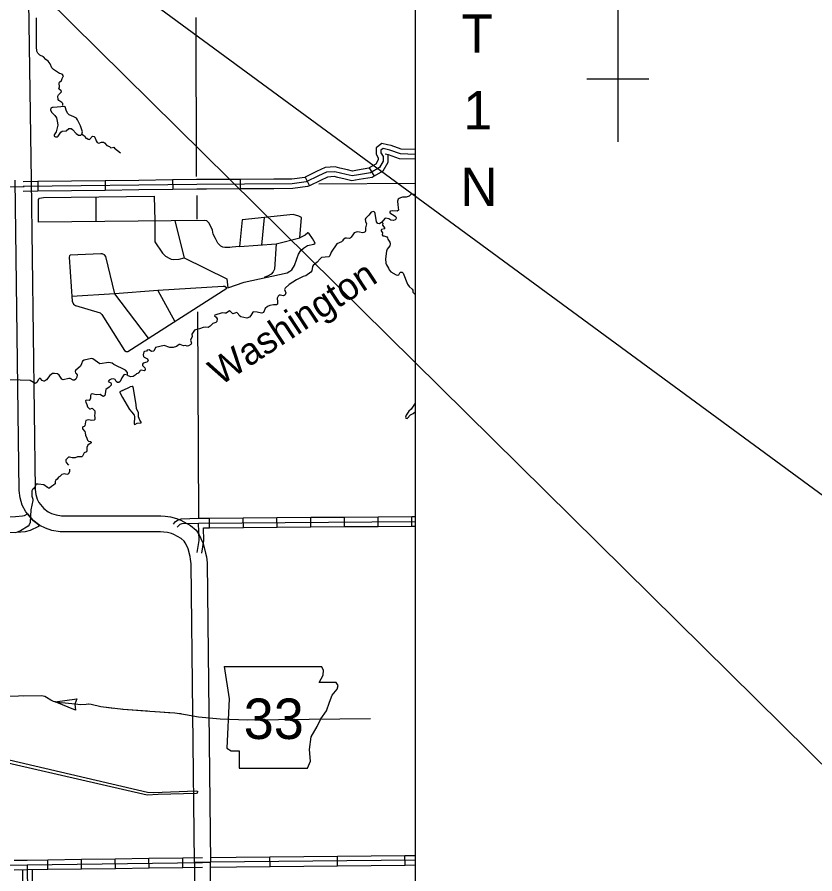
# Model space of a CAD drawing. Extents: x 982240 to 1103002, y 974866 to 1054902.
# Drawn here: x 1057609 to 1070096, y 991826 to 1005242 of the extents above; entities that cross this region are included whole.
import ezdxf

# ---------------------------------------------------------------- set-up
doc = ezdxf.new("R2010")
doc.units = 0
for name, color, linetype in [('10', 7, 'Continuous'), ('21', 7, 'Continuous'), ('31', 7, 'Continuous'), ('32', 7, 'Continuous'), ('35', 7, 'Continuous'), ('43', 7, 'Continuous'), ('45', 7, 'Continuous'), ('5', 7, 'Continuous'), ('R_Draft', 7, 'Continuous')]:
    doc.layers.add(name, color=color, linetype=linetype)

msp = doc.modelspace()

# ---------------------------------------------------------------- linework, layer by layer
at = {"layer": '10'}
for p, q in [((1059250, 997434), (1059251, 997434)), ((1060637, 992006), (1060387, 992005)), ((1060637, 992006), (1060387, 992005))]:
    msp.add_line(p, q, dxfattribs=at)
for points in [[(1057779, 1006192), (1057828, 1002691)], [(1059251, 997184), (1058283, 997180), (1058154, 997205), (1058053, 997239), (1057965, 997282), (1057854, 997364), (1057744, 997497), (1057688, 997597), (1057654, 997715), (1057641, 997828), (1057578, 1002688)], [(1057828, 1002691), (1057891, 997844), (1057900, 997764), (1057921, 997693), (1057951, 997639), (1058027, 997547), (1058095, 997497), (1058149, 997471), (1058218, 997447), (1058306, 997430), (1059250, 997434)], [(1050151, 997289), (1052347, 997337), (1057585, 997420), (1057692, 997430), (1057722, 997438), (1057772, 997463)], [(1057772, 997463), (1057854, 997364), (1057965, 997282)], [(1059251, 997434), (1059859, 997430), (1059924, 997427), (1060008, 997419), (1060106, 997393), (1060171, 997366), (1060323, 997280), (1060409, 997206), (1060460, 997134), (1060486, 997075), (1060520, 997000), (1060560, 996850), (1060572, 996791), (1060582, 996697), (1060637, 992007)], [(1057964, 997283), (1057942, 997268), (1057811, 997203), (1057737, 997183), (1057598, 997170), (1052351, 997087), (1050156, 997039)], [(1060387, 992004), (1060332, 996682), (1060325, 996753), (1060316, 996794), (1060284, 996916), (1060259, 996971), (1060241, 997009), (1060222, 997038), (1060179, 997075), (1060061, 997141), (1060025, 997156), (1059965, 997172), (1059906, 997177), (1059852, 997180), (1059249, 997184)], [(1060387, 992005), (1060415, 987556)], [(1060665, 987556), (1060637, 992006)]]:
    msp.add_lwpolyline(points, dxfattribs=at)
at = {"layer": '21'}
for p, q in [((1060850, 995073), (1060926, 994566)), ((1062406, 995014), (1062371, 995073)), ((1062339, 994820), (1062398, 994938)), ((1062398, 994938), (1062406, 995014)), ((1062601, 994820), (1062339, 994820)), ((1062635, 994777), (1062601, 994820)), ((1062618, 994718), (1062635, 994777)), ((1062542, 994625), (1062618, 994718)), ((1060926, 994566), (1060892, 993796)), ((1062449, 994380), (1062499, 994515)), ((1062499, 994515), (1062542, 994625)), ((1062364, 994253), (1062449, 994380)), ((1062305, 994135), (1062364, 994253)), ((1062212, 993974), (1062305, 994135)), ((1062186, 993771), (1062212, 993974)), ((1060892, 993796), (1060960, 993754)), ((1060960, 993754), (1061087, 993754)), ((1061087, 993754), (1061087, 993483)), ((1062203, 993593), (1062186, 993771)), ((1062152, 993483), (1062203, 993593)), ((1061087, 993483), (1062152, 993483))]:
    msp.add_line(p, q, dxfattribs=at)
msp.add_lwpolyline([(1060850, 995073), (1062371, 995073)], dxfattribs=at)
at = {"layer": '31'}
for p, q in [((1057694, 991892), (1057700, 991437)), ((1057844, 991894), (1057850, 991439))]:
    msp.add_line(p, q, dxfattribs=at)
msp.add_lwpolyline([(1057767, 991966), (1057800, 989237), (1057819, 988343)], dxfattribs=at)
at = {"layer": '32'}
for p, q in [((1060622, 997247), (1060620, 997397)), ((1061150, 997251), (1061148, 997401)), ((1061678, 997255), (1061676, 997405)), ((1062206, 997259), (1062204, 997409)), ((1062734, 997263), (1062732, 997413)), ((1063262, 997268), (1063260, 997418)), ((1063789, 997272), (1063788, 997422)), ((1060524, 997246), (1060622, 997247)), ((1058092, 991897), (1058089, 992047)), ((1058619, 991905), (1058617, 992055)), ((1059147, 991912), (1059145, 992062)), ((1059675, 991920), (1059673, 992070)), ((1060203, 991927), (1060201, 992077))]:
    msp.add_line(p, q, dxfattribs=at)
for points in [[(1060056, 997300), (1060089, 997343), (1060128, 997371), (1060178, 997387), (1060446, 997395), (1060620, 997397)], [(1060116, 997253), (1060143, 997288), (1060162, 997302), (1060191, 997311), (1060448, 997319), (1063840, 997346)], [(1060429, 996857), (1060456, 997048), (1060448, 997319)], [(1060620, 997397), (1061148, 997401)], [(1061148, 997401), (1061676, 997405)], [(1061676, 997405), (1062204, 997409)], [(1062204, 997409), (1062732, 997413)], [(1062732, 997413), (1063260, 997418)], [(1063260, 997418), (1063788, 997422)], [(1063788, 997422), (1063840, 997422)], [(1060502, 996847), (1060530, 997044), (1060524, 997246)], [(1060622, 997247), (1061150, 997251)], [(1061150, 997251), (1061678, 997255)], [(1061678, 997255), (1062206, 997259)], [(1062206, 997259), (1062734, 997263)], [(1062734, 997263), (1063262, 997268)], [(1063262, 997268), (1063789, 997272)], [(1063789, 997272), (1063840, 997272)], [(1049643, 991895), (1055029, 991939), (1057767, 991966)], [(1057562, 992041), (1057766, 992043), (1058089, 992047)], [(1057767, 991966), (1060512, 992005)], [(1058089, 992047), (1058617, 992055)], [(1058617, 992055), (1059145, 992062)], [(1059145, 992062), (1059673, 992070)], [(1059673, 992070), (1060201, 992077)], [(1060201, 992077), (1060511, 992082)], [(1057563, 991891), (1057768, 991893), (1058092, 991897)], [(1058092, 991897), (1058619, 991905)], [(1058619, 991905), (1059147, 991912)], [(1059147, 991912), (1059675, 991920)], [(1059675, 991920), (1060203, 991927)], [(1060203, 991927), (1060513, 991932)]]:
    msp.add_lwpolyline(points, dxfattribs=at)
at = {"layer": '35'}
for points in [[(1058323, 1003856), (1058326, 1003876), (1058323, 1003890), (1058311, 1003904), (1058262, 1003937), (1058252, 1003954), (1058245, 1004005), (1058257, 1004024), (1058303, 1004070), (1058299, 1004086), (1058265, 1004112), (1058262, 1004120), (1058272, 1004151), (1058268, 1004209), (1058272, 1004222), (1058302, 1004249), (1058312, 1004280), (1058332, 1004310), (1058333, 1004325), (1058315, 1004347), (1058274, 1004358), (1058239, 1004381), (1058180, 1004422), (1058151, 1004448), (1058124, 1004511), (1058097, 1004554), (1058057, 1004579), (1058021, 1004620), (1057967, 1004646), (1057933, 1004676), (1057916, 1004708), (1057910, 1004777), (1057911, 1005233)], [(1058173, 1003825), (1058156, 1003824), (1058136, 1003815), (1058131, 1003791), (1058149, 1003756), (1058201, 1003699), (1058224, 1003666), (1058241, 1003589), (1058246, 1003549), (1058220, 1003445), (1058190, 1003401), (1058188, 1003376), (1058209, 1003366), (1058239, 1003369), (1058253, 1003378), (1058293, 1003441), (1058313, 1003457), (1058374, 1003459), (1058416, 1003499), (1058454, 1003496), (1058477, 1003481), (1058533, 1003418), (1058571, 1003392), (1058605, 1003391), (1058621, 1003407), (1058631, 1003448)], [(1058631, 1003448), (1058603, 1003537), (1058554, 1003635), (1058536, 1003659), (1058499, 1003680), (1058425, 1003712), (1058403, 1003732), (1058381, 1003771), (1058363, 1003835), (1058354, 1003840), (1058173, 1003825)], [(1058621, 1003407), (1058661, 1003381), (1058683, 1003346), (1058702, 1003347), (1058722, 1003331), (1058741, 1003326), (1058790, 1003376), (1058817, 1003372), (1058825, 1003364), (1058845, 1003306), (1058864, 1003280), (1058890, 1003268), (1058929, 1003282), (1058959, 1003283), (1058976, 1003273), (1059014, 1003234), (1059057, 1003214), (1059078, 1003197), (1059122, 1003203), (1059134, 1003189), (1059225, 1003115)], [(1058022, 1002416), (1059755, 1002439)], [(1058844, 1002041), (1058844, 1002427)], [(1059755, 1002439), (1059765, 1002051), (1059762, 1001725), (1059886, 1001546), (1059934, 1001496), (1059997, 1001464)], [(1063840, 1002451), (1063818, 1002465), (1063779, 1002467), (1063760, 1002456), (1063747, 1002439), (1063700, 1002420), (1063639, 1002420), (1063611, 1002414), (1063591, 1002404), (1063574, 1002389), (1063565, 1002359), (1063570, 1002301), (1063581, 1002220), (1063556, 1002202), (1063485, 1002207), (1063453, 1002203), (1063443, 1002196), (1063445, 1002176), (1063526, 1002126), (1063538, 1002114), (1063542, 1002099), (1063537, 1002080), (1063528, 1002069), (1063499, 1002055), (1063461, 1002062), (1063427, 1002085), (1063379, 1002095), (1063363, 1002091), (1063318, 1002030)], [(1057941, 1002029), (1057943, 1002388), (1057958, 1002409), (1058022, 1002416)], [(1059997, 1001464), (1060021, 1001453), (1060054, 1001446), (1060145, 1001451), (1060224, 1001472), (1060889, 1001145), (1060906, 1001001), (1061165, 1001094), (1061837, 1001240), (1061877, 1001262), (1061911, 1001287), (1061952, 1001352), (1061985, 1001459), (1062015, 1001528), (1062050, 1001585), (1062094, 1001626), (1062155, 1001665), (1062251, 1001688), (1062274, 1001702), (1062232, 1001774), (1062177, 1001857), (1062161, 1001866), (1062117, 1001826), (1062032, 1001785), (1062061, 1002105), (1062020, 1002126), (1061928, 1002151), (1061134, 1002070), (1061091, 1001649), (1060973, 1001640), (1060937, 1001632), (1060860, 1001633), (1060829, 1001639), (1060795, 1001653), (1060753, 1001703), (1060712, 1001775), (1060680, 1001843), (1060666, 1001906), (1060616, 1002017), (1060578, 1002053), (1060544, 1002058), (1057941, 1002029)], [(1063318, 1002030), (1063282, 1002004), (1063255, 1002008), (1063236, 1002036), (1063215, 1002166), (1063207, 1002182), (1063191, 1002196), (1063172, 1002195), (1063150, 1002186), (1063116, 1002143), (1063065, 1002096), (1063055, 1002080), (1063062, 1002043), (1063078, 1002006), (1063062, 1001944), (1063063, 1001891), (1063057, 1001879), (1063038, 1001868), (1063017, 1001866), (1062966, 1001877), (1062932, 1001878), (1062886, 1001865), (1062862, 1001833), (1062840, 1001796), (1062823, 1001779), (1062809, 1001776), (1062766, 1001782), (1062744, 1001779), (1062711, 1001755), (1062704, 1001739), (1062685, 1001723), (1062615, 1001694), (1062525, 1001561), (1062505, 1001502), (1062486, 1001487), (1062375, 1001477), (1062352, 1001458), (1062308, 1001407), (1062242, 1001351), (1062231, 1001336), (1062220, 1001271), (1062206, 1001246), (1062130, 1001189), (1062084, 1001178), (1061984, 1001130), (1061868, 1001053), (1061803, 1000996), (1061794, 1000975), (1061816, 1000926), (1061804, 1000895), (1061790, 1000885), (1061774, 1000880), (1061732, 1000889), (1061711, 1000888), (1061693, 1000874), (1061679, 1000843), (1061685, 1000785)], [(1060076, 1002053), (1060224, 1001472)], [(1061478, 1002105), (1061433, 1001673)], [(1063318, 1002030), (1063333, 1002017), (1063327, 1001984), (1063349, 1001960), (1063364, 1001933), (1063360, 1001926), (1063312, 1001914), (1063306, 1001905), (1063306, 1001895), (1063327, 1001864), (1063323, 1001835), (1063335, 1001818), (1063350, 1001816), (1063395, 1001803), (1063405, 1001787), (1063412, 1001765), (1063442, 1001717), (1063447, 1001691), (1063444, 1001662), (1063402, 1001610), (1063390, 1001579), (1063377, 1001456), (1063382, 1001390), (1063389, 1001361), (1063423, 1001311), (1063433, 1001282), (1063456, 1001253), (1063544, 1001205), (1063566, 1001199), (1063585, 1001205), (1063601, 1001238), (1063612, 1001248), (1063635, 1001249), (1063651, 1001231), (1063721, 1001058), (1063746, 1001021), (1063793, 1000984), (1063801, 1000967), (1063805, 1000933), (1063840, 1000900)], [(1061091, 1001649), (1061666, 1001691), (1062032, 1001785)], [(1061666, 1001691), (1061637, 1001296), (1061619, 1001253), (1061587, 1001218), (1061541, 1001190), (1061475, 1001163)], [(1060893, 1000997), (1060862, 1001021), (1060836, 1001025), (1059810, 1000959), (1059139, 1000909), (1058995, 1001493), (1058977, 1001521), (1058941, 1001534), (1058917, 1001536), (1058441, 1001516), (1058429, 1001504), (1058426, 1001482), (1058471, 1000792), (1058489, 1000749), (1058524, 1000724), (1058911, 1000611), (1058935, 1000585), (1059291, 1000022), (1059315, 1000008), (1059340, 1000007), (1060893, 1000997)], [(1059810, 1000959), (1060076, 1000478)], [(1059667, 1000215), (1059139, 1000909), (1058467, 1000868)], [(1061685, 1000785), (1061683, 1000745), (1061668, 1000736), (1061620, 1000739), (1061563, 1000727), (1061526, 1000712), (1061491, 1000679), (1061465, 1000614), (1061439, 1000605), (1061389, 1000614), (1061365, 1000623), (1061310, 1000628), (1061297, 1000622), (1061269, 1000567), (1061247, 1000543), (1061205, 1000526), (1061110, 1000549), (1061086, 1000568), (1061075, 1000588), (1061055, 1000609), (1061042, 1000616), (1061015, 1000606), (1060985, 1000595), (1060945, 1000638), (1060934, 1000640), (1060882, 1000604), (1060858, 1000604), (1060820, 1000612), (1060703, 1000574), (1060699, 1000563), (1060727, 1000546), (1060742, 1000518), (1060737, 1000475), (1060719, 1000458), (1060671, 1000445), (1060630, 1000402), (1060598, 1000380), (1060550, 1000387), (1060520, 1000382), (1060463, 1000359), (1060402, 1000347), (1060384, 1000339), (1060344, 1000279), (1060349, 1000240), (1060324, 1000183), (1060337, 1000134), (1060329, 1000113), (1060294, 1000093), (1060273, 1000091), (1060245, 1000098), (1060214, 1000093), (1060159, 1000115), (1060143, 1000113), (1060105, 1000086), (1060049, 1000068)], [(1060049, 1000068), (1060000, 1000069), (1059909, 1000098), (1059777, 1000070), (1059747, 1000011), (1059714, 1000005), (1059678, 1000032), (1059645, 1000026), (1059633, 1000012), (1059605, 1000006), (1059594, 999998), (1059580, 999954), (1059585, 999930), (1059595, 999916), (1059648, 999890), (1059659, 999861), (1059655, 999852), (1059637, 999839), (1059583, 999822), (1059570, 999805), (1059573, 999784), (1059609, 999748), (1059615, 999728), (1059613, 999713), (1059598, 999704), (1059549, 999713), (1059536, 999706), (1059513, 999674), (1059497, 999661), (1059480, 999657), (1059471, 999645), (1059426, 999615), (1059389, 999611), (1059346, 999625), (1059336, 999634)], [(1059336, 999634), (1059336, 999675), (1059306, 999714), (1059125, 999800), (1059097, 999821), (1059042, 999833), (1058901, 999813), (1058794, 999890), (1058772, 999895), (1058658, 999871), (1058634, 999854), (1058615, 999814), (1058599, 999774), (1058522, 999706), (1058516, 999691), (1058524, 999670), (1058535, 999663), (1058547, 999642), (1058546, 999603), (1058530, 999573), (1058505, 999558), (1058487, 999556), (1058437, 999581), (1058416, 999585), (1058331, 999561), (1058310, 999573), (1058268, 999635), (1058243, 999656), (1058194, 999663), (1058165, 999661), (1058123, 999632), (1058070, 999564), (1058037, 999543), (1058026, 999541), (1057999, 999554), (1057976, 999582), (1057965, 999587), (1057946, 999568), (1057915, 999520), (1057891, 999507), (1057815, 999554), (1056697, 999590)], [(1059336, 999634), (1059290, 999647), (1059277, 999640), (1059250, 999592), (1059222, 999535), (1059200, 999521), (1059180, 999522), (1059161, 999538), (1059143, 999569), (1059117, 999577), (1059081, 999572), (1059050, 999558), (1059032, 999537), (1059077, 999514), (1059082, 999503), (1059082, 999481), (1059051, 999445), (1058998, 999409), (1058990, 999386), (1058988, 999337), (1058981, 999315), (1058960, 999303), (1058945, 999306), (1058907, 999334), (1058844, 999327), (1058802, 999340), (1058782, 999341), (1058769, 999337), (1058755, 999315), (1058757, 999277), (1058752, 999258), (1058739, 999241), (1058690, 999245), (1058681, 999234), (1058685, 999212), (1058700, 999176), (1058711, 999139), (1058742, 999109), (1058759, 999108), (1058782, 999119), (1058824, 999077), (1058824, 999041), (1058820, 999000), (1058826, 998970), (1058824, 998942), (1058815, 998932), (1058776, 998926), (1058726, 998936), (1058684, 998925), (1058677, 998907), (1058671, 998844), (1058657, 998831), (1058639, 998824), (1058630, 998809), (1058632, 998793)], [(1059260, 999397), (1059219, 999376), (1059217, 999365), (1059257, 999287), (1059370, 999097), (1059404, 999056), (1059439, 999011), (1059445, 998986), (1059441, 998870), (1059454, 998861), (1059488, 998883), (1059551, 998889), (1059552, 998898), (1059529, 998932), (1059511, 998984), (1059508, 999044), (1059475, 999113), (1059472, 999170), (1059433, 999424), (1059418, 999457), (1059412, 999458), (1059376, 999452)], [(1059260, 999397), (1059376, 999452)], [(1063840, 999195), (1063776, 999105), (1063739, 999071), (1063700, 999009), (1063689, 998975), (1063692, 998960), (1063712, 998958), (1063766, 999012), (1063808, 999035), (1063840, 999062)], [(1058632, 998793), (1058667, 998754), (1058676, 998731), (1058680, 998694), (1058702, 998649), (1058710, 998615), (1058726, 998601), (1058757, 998594), (1058768, 998587), (1058770, 998577), (1058716, 998539), (1058701, 998505), (1058699, 998448), (1058693, 998437), (1058659, 998417), (1058634, 998365), (1058622, 998355), (1058553, 998357), (1058520, 998343), (1058473, 998342), (1058429, 998352), (1058412, 998349), (1058390, 998332), (1058370, 998307), (1058369, 998291), (1058375, 998267), (1058415, 998225)], [(1058429, 998165), (1058427, 998125), (1058414, 998092), (1058404, 998084), (1058387, 998080), (1058348, 998088), (1058328, 998086), (1058309, 998078), (1058279, 998047), (1058258, 998036), (1058235, 998005), (1058215, 997992), (1058203, 997972), (1058205, 997936), (1058179, 997915), (1058147, 997894), (1058114, 997867), (1058101, 997864), (1058082, 997874), (1058025, 997918), (1057937, 997929), (1057905, 997926), (1057896, 997913), (1057889, 997892), (1057863, 997857), (1057848, 997847), (1057837, 997825), (1057840, 997741), (1057854, 997695), (1057856, 997672), (1057824, 997529), (1057813, 997326), (1057800, 997293), (1057784, 997272), (1057664, 997198), (1057585, 997168)], [(1057485, 993614), (1059648, 993103), (1059743, 993102), (1060412, 993128), (1060430, 993123), (1060434, 993111), (1060427, 993092), (1060409, 993082), (1059815, 993069), (1059645, 993058), (1056506, 993781)]]:
    msp.add_lwpolyline(points, dxfattribs=at)
at = {"layer": '43'}
for p, q in [((1058207, 994518), (1058546, 994567)), ((1058525, 994390), (1058207, 994518)), ((1058546, 994567), (1058513, 994482)), ((1058512, 994481), (1058525, 994390))]:
    msp.add_line(p, q, dxfattribs=at)
for points in [[(1063138, 994254), (1061218, 994232), (1060789, 994251), (1060449, 994279), (1060247, 994317), (1060151, 994334), (1060075, 994343), (1059686, 994369), (1059269, 994401), (1058917, 994442), (1058768, 994476), (1058724, 994483), (1058689, 994477), (1058603, 994473), (1058515, 994481), (1058363, 994501), (1058283, 994505), (1058237, 994512), (1058177, 994525), (1058137, 994548), (1058071, 994590), (1058042, 994605), (1058016, 994610), (1057988, 994613), (1055091, 994574)], [(1058092, 994577), (1058071, 994590), (1058042, 994605), (1058016, 994610), (1057988, 994613), (1057704, 994609)], [(1058601, 994473), (1058515, 994481), (1058363, 994501), (1058283, 994505), (1058237, 994512), (1058208, 994518)], [(1059123, 994418), (1058917, 994442), (1058768, 994476), (1058732, 994482)], [(1059649, 994372), (1059269, 994401), (1059254, 994403)], [(1059978, 994349), (1059780, 994362)], [(1060175, 994330), (1060151, 994334), (1060075, 994343), (1059978, 994349)]]:
    msp.add_lwpolyline(points, dxfattribs=at)
at = {"layer": '45'}
for p, q in [((1063121, 1002880), (1063197, 1002751)), ((1060042, 1002693), (1060044, 1002543)), ((1061099, 1002701), (1061100, 1002551)), ((1062118, 1002737), (1062184, 1002602)), ((1057931, 1002666), (1057932, 1002516)), ((1058986, 1002679), (1058988, 1002529)), ((1061569, 991941), (1061567, 992091)), ((1062625, 991953), (1062623, 992103)), ((1063681, 991964), (1063679, 992114)), ((1063840, 992040), (1060637, 992007)), ((1063840, 992040), (1060637, 992007))]:
    msp.add_line(p, q, dxfattribs=at)
for points in [[(1063404, 1003243), (1063320, 1003263), (1063229, 1003195), (1063229, 1003096), (1063262, 1003039), (1063262, 1003005), (1063224, 1002941), (1063121, 1002880)], [(1063840, 1003168), (1063622, 1003174), (1063465, 1003229), (1063404, 1003243)], [(1063840, 1003093), (1063608, 1003100), (1063444, 1003157), (1063337, 1003182), (1063304, 1003157), (1063304, 1003116), (1063337, 1003059), (1063337, 1002985), (1063279, 1002886), (1063140, 1002804), (1062951, 1002771), (1062852, 1002754), (1062761, 1002779), (1062581, 1002820), (1062449, 1002812), (1062326, 1002754), (1062131, 1002660), (1061916, 1002631), (1060420, 1002623), (1057704, 1002588)], [(1063406, 1003089), (1063412, 1003078), (1063412, 1002964), (1063334, 1002831), (1063197, 1002751)], [(1063840, 1003018), (1063594, 1003025), (1063423, 1003085), (1063371, 1003097)], [(1062662, 1002878), (1062587, 1002896), (1062430, 1002886), (1062294, 1002822), (1062118, 1002737)], [(1063121, 1002880), (1063113, 1002875), (1062938, 1002845), (1062856, 1002831), (1062780, 1002852), (1062662, 1002878)], [(1059514, 1002686), (1058986, 1002679)], [(1060042, 1002693), (1059514, 1002686)], [(1060571, 1002699), (1060419, 1002698), (1060042, 1002693)], [(1061099, 1002701), (1060571, 1002699)], [(1061627, 1002704), (1061099, 1002701)], [(1062118, 1002737), (1062110, 1002733), (1061911, 1002706), (1061627, 1002704)], [(1062628, 1002732), (1062574, 1002744), (1062468, 1002738), (1062358, 1002686), (1062184, 1002602)], [(1063197, 1002751), (1063166, 1002732), (1062963, 1002697), (1062848, 1002678), (1062743, 1002706), (1062628, 1002732)], [(1057931, 1002666), (1057703, 1002663)], [(1058459, 1002673), (1057931, 1002666)], [(1058986, 1002679), (1058459, 1002673)], [(1061100, 1002551), (1060572, 1002549)], [(1061628, 1002554), (1061100, 1002551)], [(1062184, 1002602), (1062153, 1002588), (1061922, 1002556), (1061628, 1002554)], [(1057932, 1002516), (1057705, 1002513)], [(1058460, 1002523), (1057932, 1002516)], [(1058988, 1002529), (1058460, 1002523)], [(1059516, 1002536), (1058988, 1002529)], [(1060044, 1002543), (1059516, 1002536)], [(1060572, 1002549), (1060420, 1002548), (1060044, 1002543)], [(1061039, 992086), (1061567, 992091)], [(1061567, 992091), (1062095, 992097)], [(1062095, 992097), (1062623, 992103)], [(1062623, 992103), (1063151, 992108)], [(1063151, 992108), (1063679, 992114)], [(1063679, 992114), (1063840, 992115)], [(1060636, 992082), (1061039, 992086)], [(1062097, 991947), (1062625, 991953)], [(1062625, 991953), (1063153, 991958)], [(1063153, 991958), (1063681, 991964)], [(1063681, 991964), (1063840, 991965)], [(1060638, 991932), (1061041, 991936)], [(1061041, 991936), (1061569, 991941)], [(1061569, 991941), (1062097, 991947)]]:
    msp.add_lwpolyline(points, dxfattribs=at)
at = {"layer": '5'}
for points in [[(1060419, 1002746), (1060412, 1005234)], [(1055089, 1002555), (1057717, 1002588)], [(1062333, 1002633), (1063840, 1002641)], [(1060420, 1002449), (1060422, 1002080)], [(1060421, 1002405), (1060422, 1002080)], [(1060430, 1000627), (1060447, 997395)]]:
    msp.add_lwpolyline(points, dxfattribs=at)
at = {"layer": 'R_Draft'}
for p, q in [((1067016, 1003291), (1067016, 1011715)), ((1071250, 996988), (1057667, 1006974)), ((1071250, 992513), (1057678, 1005924)), ((1066527, 1004275), (1067499, 1004275))]:
    msp.add_line(p, q, dxfattribs=at)
msp.add_lwpolyline([(1018617, 1018049), (1063840, 1018049), (1063840, 987556), (1018617, 987556)], close=True, dxfattribs=at)
msp.add_lwpolyline([(1018617, 1018049), (1063840, 1018049), (1063840, 987556), (1018617, 987556)], close=True, dxfattribs=at)

# ---------------------------------------------------------------- texts
at = {"layer": '21'}
msp.add_text('33', height=633.6, dxfattribs=at).set_placement((1061155, 993938))
at = {"layer": '35'}
msp.add_text('Washington', height=422.4, rotation=33.3939, dxfattribs=at).set_placement((1060787, 999461))
at = {"layer": 'R_Draft'}
for s, p in [('T', (1064564, 1004684)), ('1', (1064597, 1003484)), ('N', (1064548, 1002284))]:
    msp.add_text(s, height=600, dxfattribs=at).set_placement(p)

doc.saveas('drawing.dxf')
